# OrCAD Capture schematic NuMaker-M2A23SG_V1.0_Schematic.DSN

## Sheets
1 Nu-Link2-Me: size A3; title: Nu-Link2-Me; rev: 3.2; company: CMHuang; note: Nu-Link2-Me
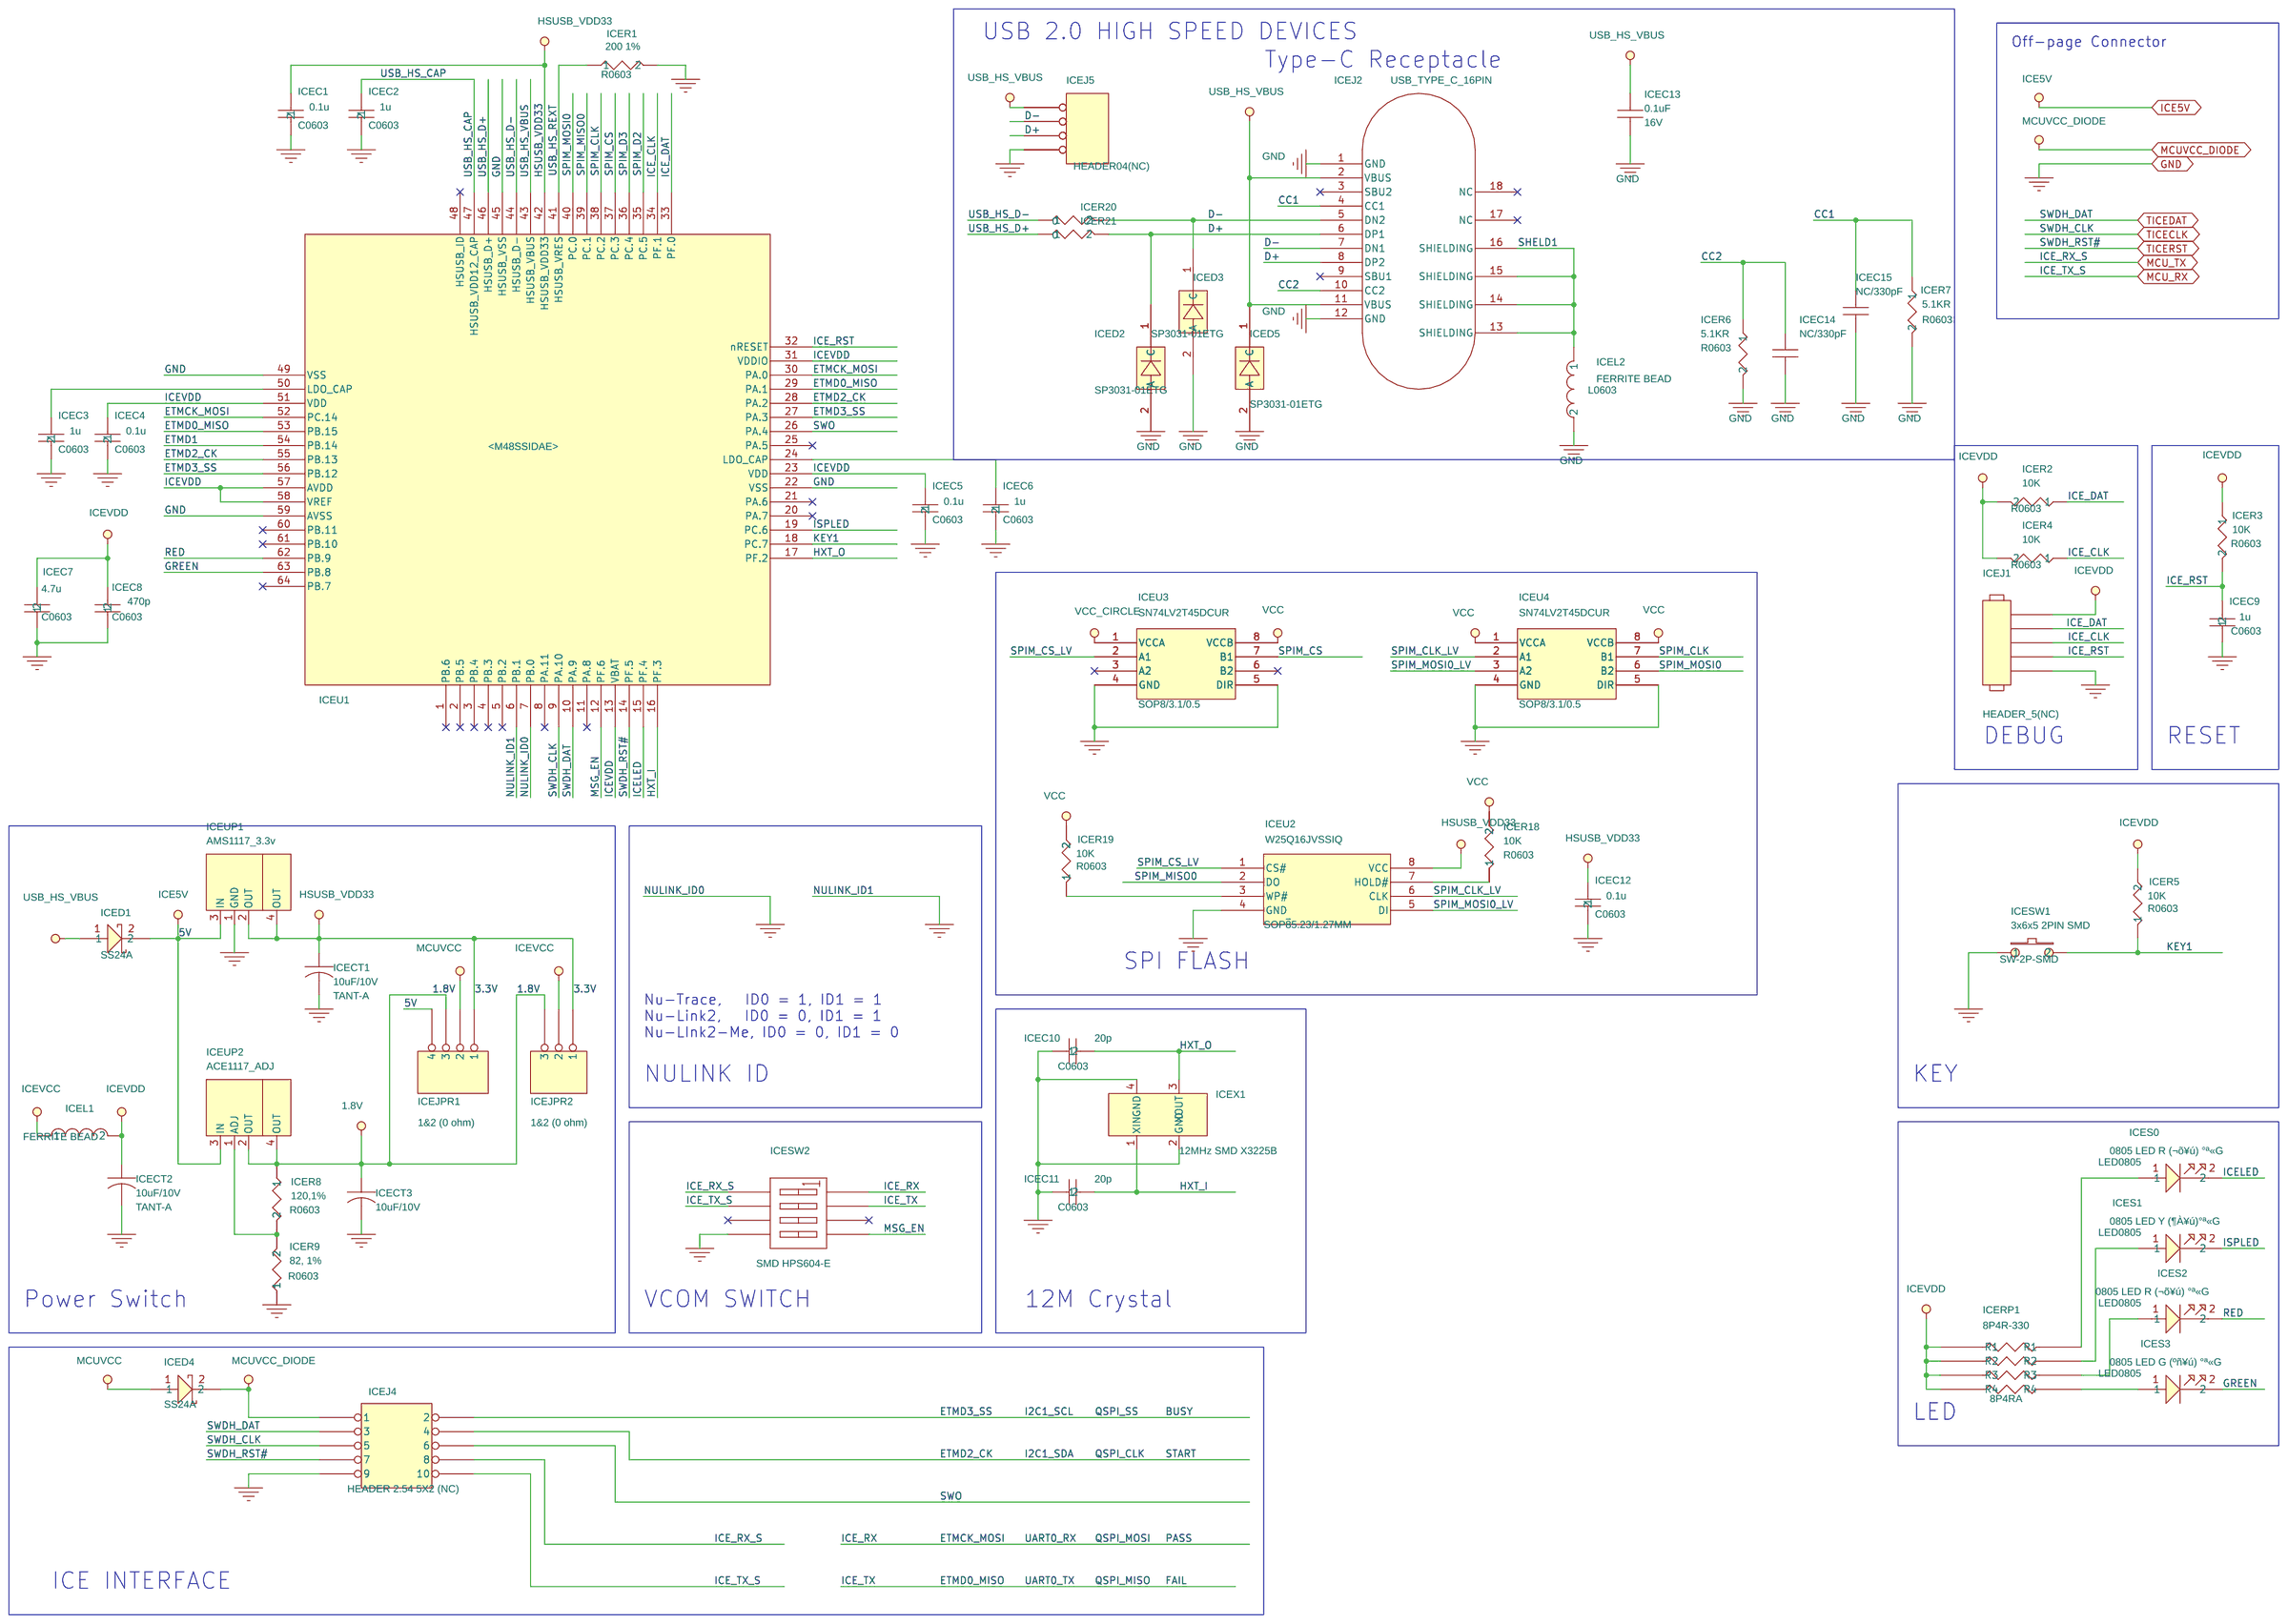
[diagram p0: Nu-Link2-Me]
2 M2A23: size Custom; title: M2A23SG5AC; rev: v1.0; note: NuMaker-M2A23SG
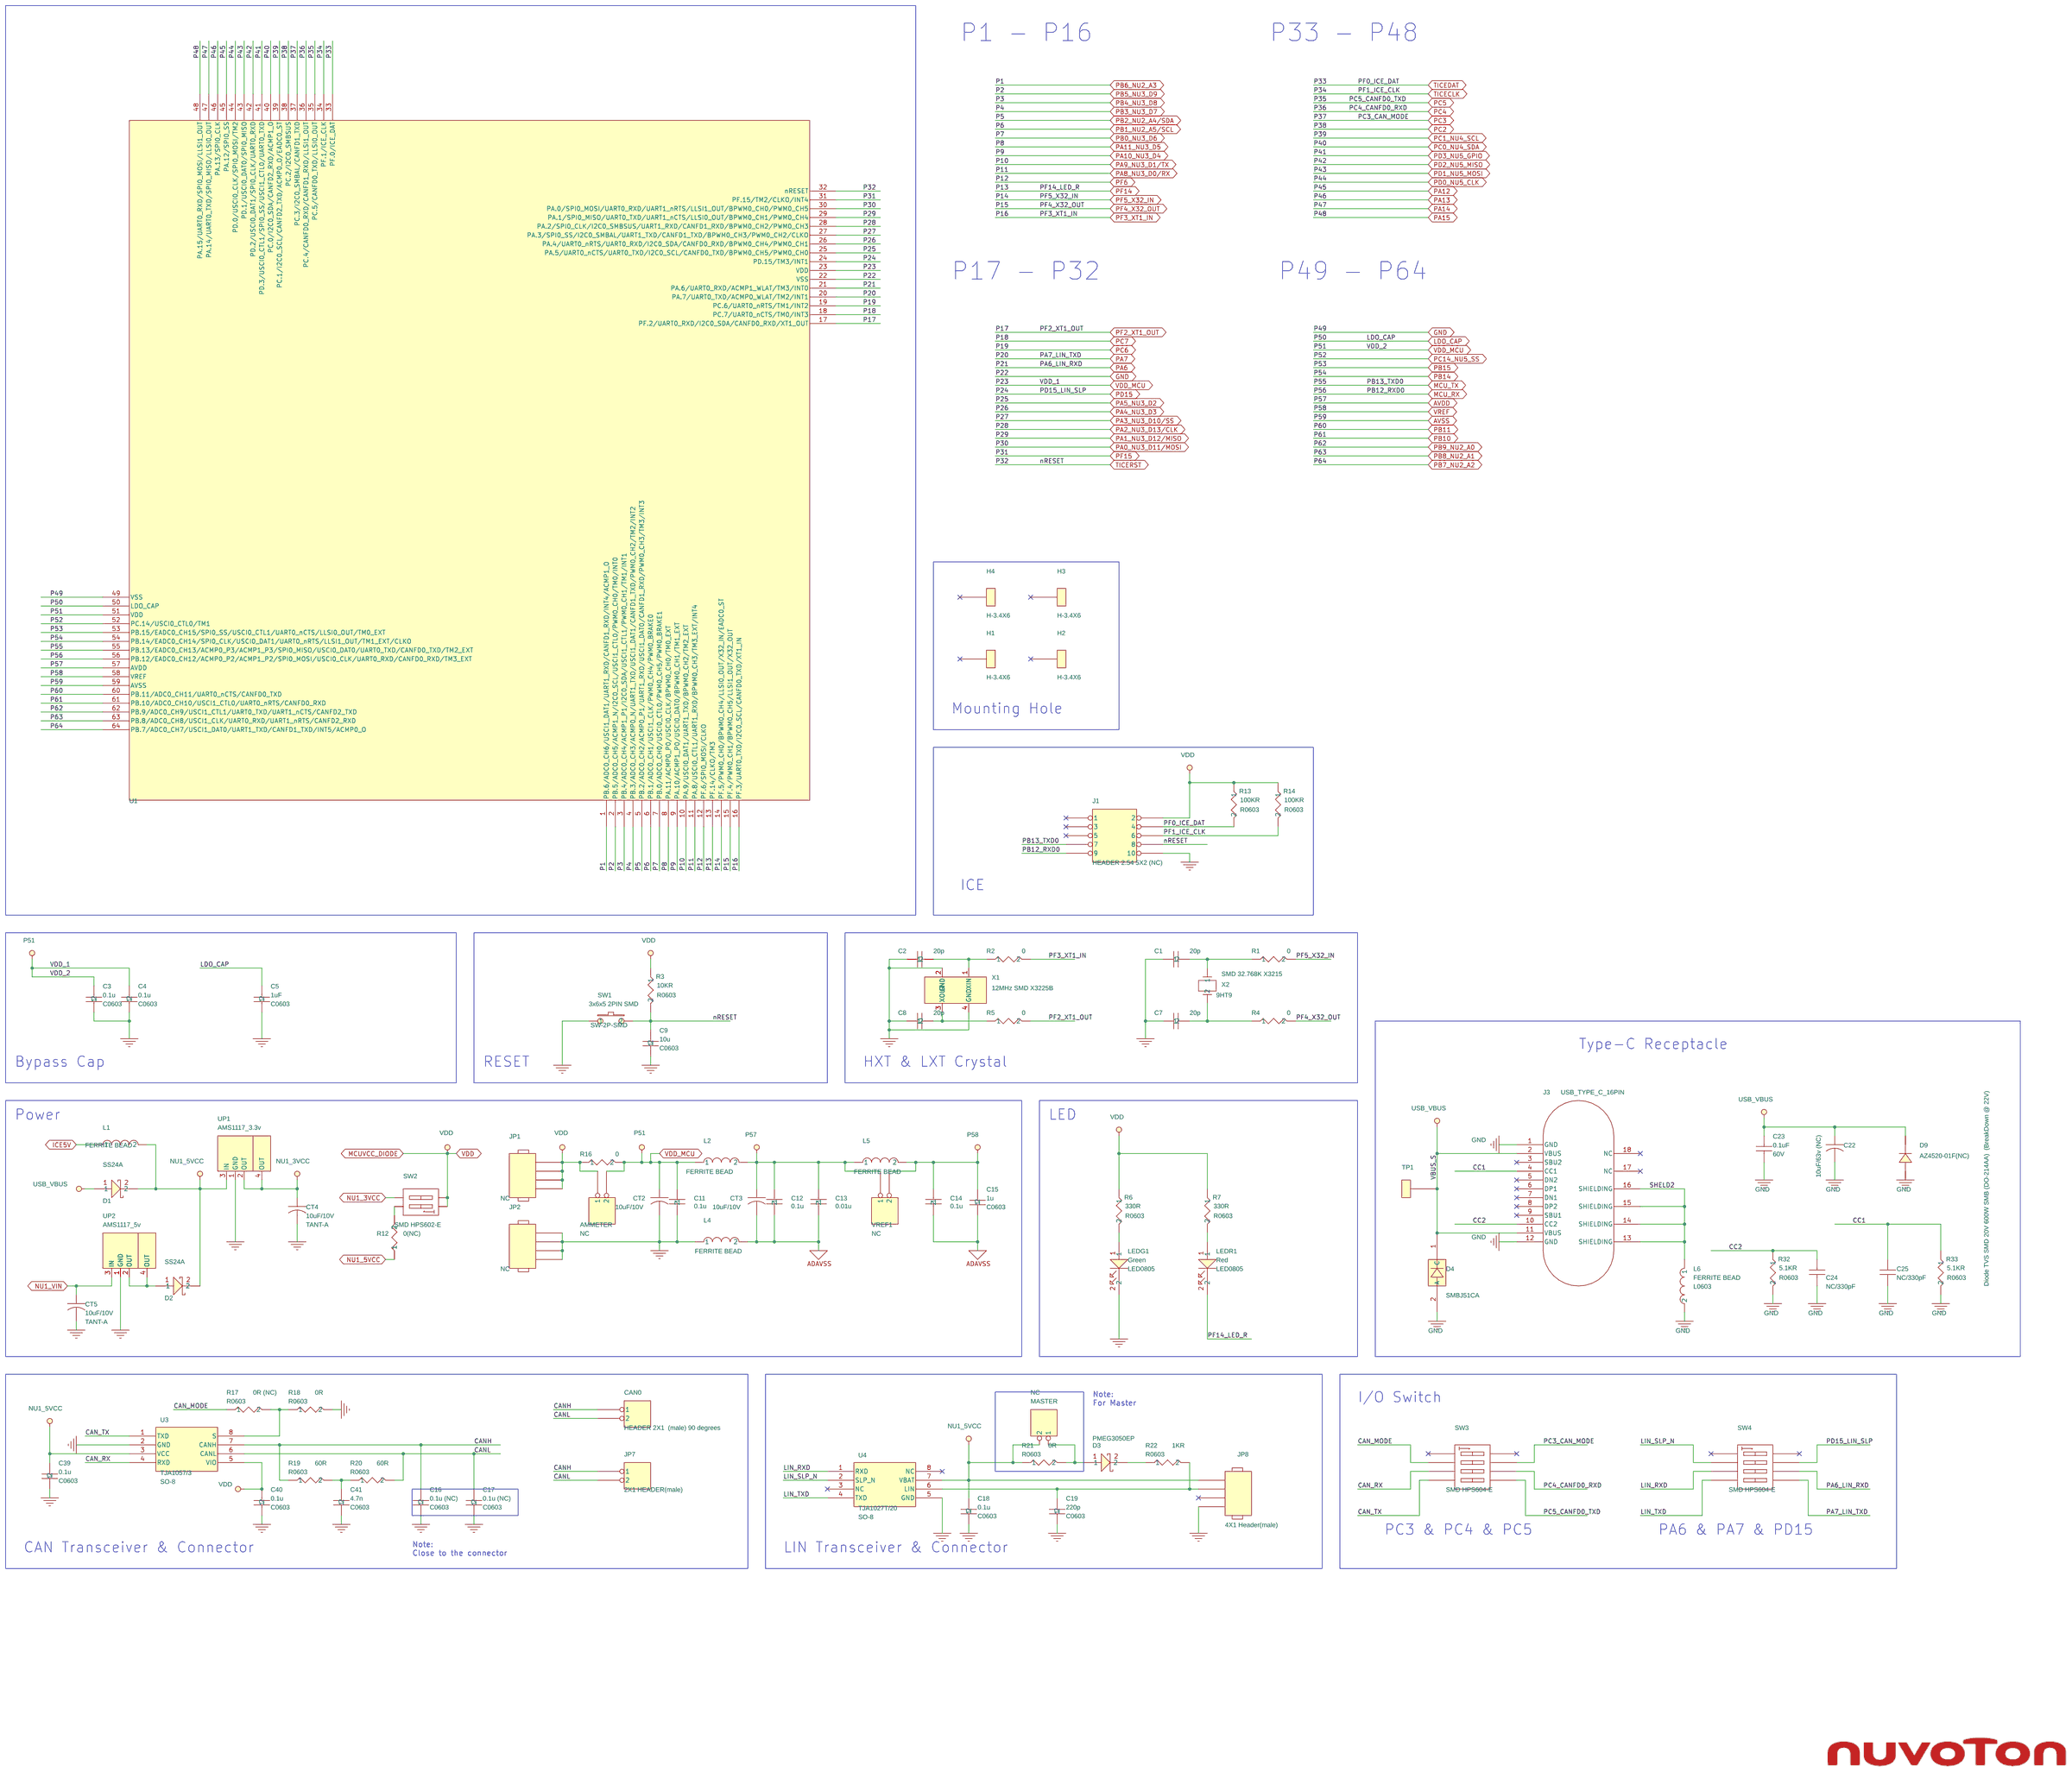
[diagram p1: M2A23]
3 Ext. Connector: size Custom; title: Ext. Connector; rev: v1.0; note: NuMaker-M2A23SG
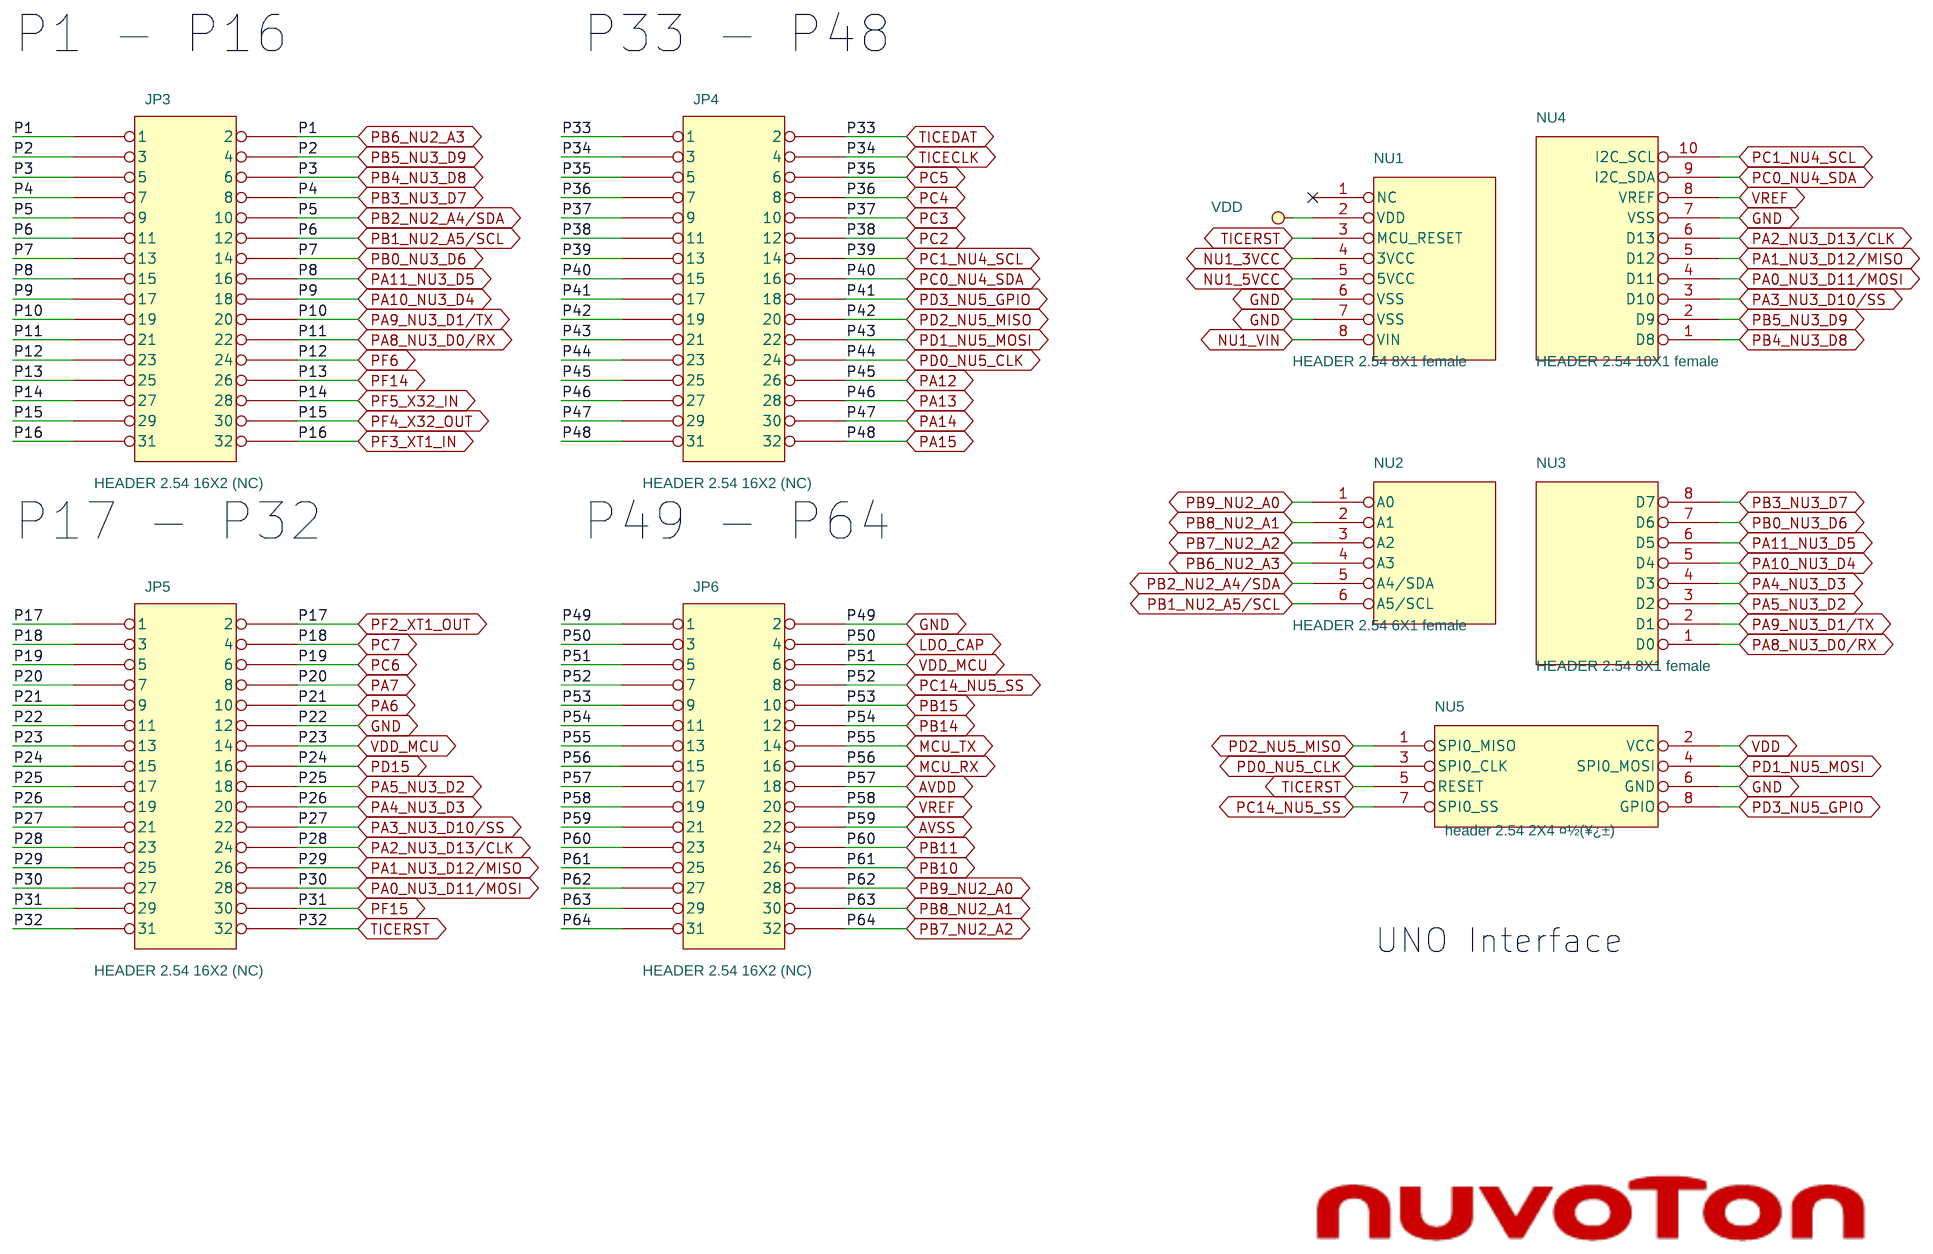
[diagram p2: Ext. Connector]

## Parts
sheet Ext. Connector
JP3  HEADER 2.54 16X2 (NC)  [HEADER16X2]
JP4  HEADER 2.54 16X2 (NC)  [HEADER16X2]
JP5  HEADER 2.54 16X2 (NC)  [HEADER16X2]
JP6  HEADER 2.54 16X2 (NC)  [HEADER16X2]
NU1  HEADER 2.54 8X1 female  [SIP-8P]
NU2  HEADER 2.54 6X1 female  [SIP-6P]
NU3  HEADER 2.54 8X1 female  [SIP-8P]
NU4  HEADER 2.54 10X1 female  [SIP-10P]
NU5  header 2.54 2X4 ¤½(¥¿­±)  [HEADER4X2]
sheet M2A23
AMMETER  NC  [HEADER2X1]
C1  20p  [C0603]
C2  20p  [C0603]
C3  0.1u  [C0603]
C4  0.1u  [C0603]
C5  1uF  [C0603]
C7  20p  [C0603]
C8  20p  [C0603]
C9  10u  [C0603]
C11  0.1u  [C0603]
C12  0.1u  [C0603]
C13  0.01u  [C0603]
C14  0.1u  [C0603]
C15  1u  [C0603]
C16  0.1u (NC)  [C0603]
C17  0.1u (NC)  [C0603]
C18  0.1u  [C0603]
C19  220p  [C0603]
C22  10uF/63v (NC)  [CES/6.3D/P]
C23  0.1uF  [C0603]
C24  NC/330pF  [C0603]
C25  NC/330pF  [C0603]
C39  0.1u  [C0603]
C40  0.1u  [C0603]
C41  4.7n  [C0603]
CAN0  HEADER 2X1  (male) 90 degrees  [SIP/2P_3.5MM]
CT2  10uF/10V  [TANT-A]
CT3  10uF/10V  [TANT-A]
CT4  10uF/10V  [TANT-A]
CT5  10uF/10V  [TANT-A]
D1  SS24A  [RB060L]
D2  SS24A  [RB060L]
D3  PMEG3050EP  [SOD-123-A(B)]
D4  SMBJ51CA  [DO-214AA]
D9  AZ4520-01F(NC)  [DO-214AA/SMB]
H1  H-3.4X6  [H-3.4X6]
H2  H-3.4X6  [H-3.4X6]
H3  H-3.4X6  [H-3.4X6]
H4  H-3.4X6  [H-3.4X6]
J1  HEADER 2.54 5X2 (NC)  [HEADER5X2]
J3  USB_TYPE_C_16PIN  [TID(00302-UCAF003-N)]
JP1  NC  [header1x4]
JP2  NC  [header1x4]
JP7  2X1 HEADER(male)  [HEADER2X1]
JP8  4X1 Header(male)  [header1x4]
L1  FERRITE BEAD  [L0603]
L2  FERRITE BEAD  [L0603]
L4  FERRITE BEAD  [L0603]
L5  FERRITE BEAD  [L0603]
L6  FERRITE BEAD  [L0603]
LEDG1  Green  [LED0805]
LEDR1  Red  [LED0805]
MASTER  NC  [HEADER2X1]
R1  0  [R0603]
R2  0  [R0603]
R3  10KR  [R0603]
R4  0  [R0603]
R5  0  [R0603]
R6  330R  [R0603]
R7  330R  [R0603]
R12  0(NC)  [R0603]
R13  100KR  [R0603]
R14  100KR  [R0603]
R16  0  [R0603]
R17  0R (NC)  [R0603]
R18  0R  [R0603]
R19  60R  [R0603]
R20  60R  [R0603]
R21  0R  [R0603]
R22  1KR  [R0603]
R32  5.1KR  [R0603]
R33  5.1KR  [R0603]
SW1  3x6x5 2PIN SMD  [SW-2P-SMD]
SW2  SMD HPS602-E  [SW1X2]
SW3  SMD HPS604-E  [SW1X4]
SW4  SMD HPS604-E  [SW1X4]
TP1  TEST_POINT
U1  M2A23SG5AC  [MCU_LQFP64_7X7mm]
U3  TJA1057/3  [SO-8]
U4  TJA1027T/20  [SO-8]
UP1  AMS1117_3.3v  [SOT-223-1]
UP2  AMS1117_5v  [SOT-223-1]
VREF1  NC  [HEADER2X1]
X1  12MHz SMD X3225B  [CRYSTAL_SMD]
X2  SMD 32.768K X3215  [9HT9]
sheet Nu-Link2-Me
ICEC1  0.1u  [C0603]
ICEC2  1u  [C0603]
ICEC3  1u  [C0603]
ICEC4  0.1u  [C0603]
ICEC5  0.1u  [C0603]
ICEC6  1u  [C0603]
ICEC7  4.7u  [C0603]
ICEC8  470p  [C0603]
ICEC9  1u  [C0603]
ICEC10  20p  [C0603]
ICEC11  20p  [C0603]
ICEC12  0.1u  [C0603]
ICEC13  0.1uF  [C0603]
ICEC14  NC/330pF  [C0603]
ICEC15  NC/330pF  [C0603]
ICECT1  10uF/10V  [TANT-A]
ICECT2  10uF/10V  [TANT-A]
ICECT3  10uF/10V  [TANT-A]
ICED1  SS24A  [RB060L]
ICED2  SP3031-01ETG  [SOD882]
ICED3  SP3031-01ETG  [SOD882]
ICED4  SS24A  [RB060L]
ICED5  SP3031-01ETG  [SOD882]
ICEJ1  HEADER_5(NC)  [HEADER5X1]
ICEJ2  USB_TYPE_C_16PIN  [TID(00302-UCAF003-N)]
ICEJ4  HEADER 2.54 5X2 (NC)  [HEADER5X2]
ICEJ5  HEADER04(NC)  [HEADER04]
ICEJPR1  1&2 (0 ohm)  [R0603X3]
ICEJPR2  1&2 (0 ohm)  [R0603X2]
ICEL1  FERRITE BEAD  [L0603]
ICEL2  FERRITE BEAD  [L0603]
ICER1  200 1%  [R0603]
ICER2  10K  [R0603]
ICER3  10K  [R0603]
ICER4  10K  [R0603]
ICER5  10K  [R0603]
ICER6  5.1KR  [R0603]
ICER7  5.1KR  [R0603]
ICER8  120,1%  [R0603]
ICER9  82, 1%  [R0603]
ICER18  10K  [R0603]
ICER19  10K  [R0603]
ICER20  0  [R0603]
ICER21  0  [R0603]
ICERP1  8P4R-330  [8P4RA]
ICES0  0805 LED R (¬õ¥ú) °ª«G  [LED0805]
ICES1  0805 LED Y (¶À¥ú)°ª«G  [LED0805]
ICES2  0805 LED R (¬õ¥ú) °ª«G  [LED0805]
ICES3  0805 LED G (ºñ¥ú) °ª«G  [LED0805]
ICESW1  3x6x5 2PIN SMD  [SW-2P-SMD]
ICESW2  SMD HPS604-E  [SW1X4]
ICEU1  M48SSIDAE  [LQFP64_7x7_M48SSIDAE]
ICEU2  W25Q16JVSSIQ  [SOP8\5.23/1.27MM]
ICEU3  SN74LV2T45DCUR  [SOP8/3.1/0.5]
ICEU4  SN74LV2T45DCUR  [SOP8/3.1/0.5]
ICEUP1  AMS1117_3.3v  [SOT-223-1]
ICEUP2  ACE1117_ADJ  [SOT-223-1]
ICEX1  12MHz SMD X3225B  [CRYSTAL_SMD]

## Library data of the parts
JP3 = HEADER_16X2_3
JP4 = HEADER_16X2
JP5 = HEADER_16X2_1
JP6 = HEADER_16X2_2
NU1 = POWER_CONNECT_0
NU2 = ADC_CONNECT_0
NU3 = PWM0_CONNECT_0
NU4 = PWM1_CONNECT_1
NU5 = NuEdu_NU7
AMMETER = HEADER_2
C1 = C_20p_2
C2 = C_20p_3
C3 = CAP-C_3: Package: 0603; element_no: C0004
C4 ICEC12 = CAP-C_7: Package: 0603; element_no: C0004
C5 = CAP-C_10: Package: 0603; element_no: C0006
C7 = C_20p
C8 = C_20p_1
C9 = CAP-C: Package: 0603; element_no: C0006
C11 = C_0.1u_2: element_no: C0004
C12 = C_0.1u_3: element_no: C0004
C13 = C_0.1u: element_no: C0003
C14 = C_0.1u_1: element_no: C0004
C15 = CAP-C_8: Package: 0603; element_no: C0006
C16 = CAP-C_6: Package: 0603; element_no: C0006
C17 = CAP-C_2: Package: 0603; element_no: C0006
C18 ICEC3 = CAP-C_11: Package: 0603; element_no: C0006
C19 ICEC9 = CAP-C_5: Package: 0603; element_no: C0006
C22 CT2-CT5 ICECT1-ICECT3 = C_10uF_10V
C23 = CAPACITOR_NP: CAP CER X7R SMD 0.1uF 10% 50V 0603; Mount: M; Part Number: 880600286; Part Type: Capacitor\Ceramic; Raing/Power: 60V; Tolerance: 10%
C24 C25 ICEC14 ICEC15 = CAPACITOR_NP: CAP CER NPO SMD 330pF 5% 50V 0603; Mount: M; Part Number: 880600252; Part Type: Capacitor\Ceramic; Raing/Power: 50V; Tolerance: 5%
C39 = CAP-C_4: Package: 0603; element_no: C0006
C40 = CAP-C_1: Package: 0603; element_no: C0006
C41 ICEC2 = CAP-C_9: Package: 0603; element_no: C0006
CAN0 = HEADER_2_2
D1 = D_SS24A_2
D2 ICED1 = D_SS24A
D3 ICED4 = D_SS24A_1
D4 = Schottky_Barrier_Diode_0: Diode SMD Schottky Barrier 30V; Mount: M; Part Number: 880900908
D9 = DIODE21: Diode TVS SMD 20V 600W SMB (DO-214AA)  (BreakDown @ 22V); Mount: M; Part Number: 880900866; Part Type: Diode
H1-H4 TP1 = TEST_POINT
ICEJ4 J1 = HEADER_5X2
J3 = USB_TYPE_C_9: CON USB 3.0 Type C receptical SMD & TH; Mount: M; Part Number: 880400981; Part Type: Connector
JP1 JP2 JP8 = HEADER_4_v2
JP7 = HEADER_2_3
L1 = FERRITE_BEAD_4
L2 = FERRITE_BEAD_2
ICEL1 L4 = FERRITE_BEAD_1
L5 = FERRITE_BEAD_3
ICEL2 L6 = FERRITE_BEAD
ICES2 LEDG1 = LED_0_1: Package: KP-2012; Vendor: Kingbright
ICES1 LEDR1 = LED_0: Package: KP-2012; Vendor: Kingbright
MASTER = HEADER_2_0
R1 = R_0_16
R2 = R_0_5
ICER6 R3 = R_0_10: Package: 0603
R4 = R_0_15
R5 = R_0_18
ICER7 R6 = R_0_6: Package: 0603
ICER8 R7 = R_0_3: Package: 0603
R12 = R_0_7
ICER5 R13 = R_0: Package: 0603
ICER2 R14 = R_0_2: Package: 0603
R16 = R_0_14
ICER19 R17 = R_0_1: Package: 0603
R18 = R_0_13: Package: 0603
R19 = R_0_11: Package: 0603
R20 = R_0_12: Package: 0603
ICER1 R21 = R_0_4: Package: 0603
ICER9 R22 = R_0_9: Package: 0603
R32 = R_0_17: Package: 0603
ICER4 R33 = R_0_8: Package: 0603
ICESW1 SW1 = SW_PUSHBUTTON_0
SW2 = SW_DIP-4_2
ICESW2 SW3 SW4 = SW_DIP-4_SM
U1 = M2A23SG5AC
U3 = TJA1057_3
U4 = TJA1027T_20
ICEUP1 UP1 UP2 = TO-247_Regulator_10
VREF1 = HEADER_2_1
ICEX1 X1 = Crystal_SMD_1
X2 = Xtal_32.768K
ICEC1 = CAP-C_8: Package: 0603; element_no: C0004
ICEC4 = CAP-C_1: Package: 0603; element_no: C0004
ICEC5 = CAP-C_4: Package: 0603; element_no: C0004
ICEC6 = CAP-C_3: Package: 0603; element_no: C0006
ICEC7 = CAP-C: Package: 0603
ICEC8 = CAP-C_6: Package: 0603
ICEC10 = CAP-C_2: Package: 0603
ICEC11 = CAP-C_10: Package: 0603
ICEC13 = CAPACITOR_NP: CAP CER X7R SMD 0.1uF 10% 50V 0603; Mount: M; Part Number: 880600286; Part Type: Capacitor\Ceramic; Raing/Power: 16V; Tolerance: 10%
ICED2 ICED3 ICED5 = Schottky_Barrier_Diode_1: Diode SMD Schottky Barrier 30V; Mount: M; Part Number: 880900908
ICEJ1 = HEADER_5
ICEJ2 = USB_TYPE_C_10: CON USB 3.0 Type C receptical SMD & TH; Mount: M; Part Number: 880400981; Part Type: Connector
ICEJ5 = HEADER_4
ICEJPR1 = HEADER_3_0
ICEJPR2 = HEADER_3
ICER3 = R_0_5: Package: 0603
ICER18 = R_0_7: Package: 0603
ICER20 = R_33_1
ICER21 = R_33
ICERP1 = R-PACK8_0
ICES0 = LED_0_3: Package: KP-2012; Vendor: Kingbright
ICES3 = LED_0_2: Package: KP-2012; Vendor: Kingbright
ICEU1 = M487SIDAE_0: M487SIDAE: <M48SSIDAE>
ICEU2 = W25P10_20_40_SOIC_0: Package: SOP8; Vendor: WINBOND
ICEU3 ICEU4 = SN74LV2T45
ICEUP2 = TO-247_Regulator_0

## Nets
1.8V: ICECT3.1 ICEJPR1.3 ICEJPR2.3 ICER8.1 ICEUP2.2(OUT) ICEUP2.4(OUT)
3.3V: ICEC1.1 ICEC12.1 ICECT1.1 ICEJPR1.1 ICEJPR2.1 ICER18.2 ICER19.2 ICEU1.42(HSUSB_VDD33) ICEU2.8(VCC) ICEU3.1(VCCA) ICEU4.1(VCCA) ICEUP1.2(OUT) ICEUP1.4(OUT)
AVDD: C12.1 C13.1 CT3.1 JP6.17 JP6.18 L2.2 L5.1 U1.57(AVDD) VREF1.1
AVSS: C12.2 C13.2 C14.2 C15.1 CT3.2 JP6.21 JP6.22 L4.2 U1.59(AVSS)
GND: C1.1 C2.1 C3.1 C4.1 C5.1 C7.1 C8.1 C9.1 C11.2 C16.1 C17.1 C18.1 C19.1 C22.2 C23.2 C24.2 C25.2 C39.1 C40.1 C41.1 CT2.2 CT4.2 CT5.2 D4.2(A) D9.2(A) ICEC1.2 ICEC2.2 ICEC3.2 ICEC4.2 ICEC5.2 ICEC6.2 ICEC7.1 ICEC8.1 ICEC9.1 ICEC10.1 ICEC11.1 ICEC12.2 ICEC13.2 ICEC14.2 ICEC15.2 ICECT1.2 ICECT2.2 ICECT3.2 ICED2.2(A) ICED3.2(A) ICED5.2(A) ICEJ1.5 ICEJ2.1(GND) ICEJ2.12(GND) ICEJ4.9 ICEJ5.4 ICEL2.2 ICER1.2 ICER6.2 ICER7.2 ICER9.1 ICESW1.1 ICESW2.4(A4) ICEU1.6(PB.1) ICEU1.7(PB.0) ICEU1.22(VSS) ICEU1.45(HSUSB_VSS) ICEU1.49(VSS) ICEU1.59(AVSS) ICEU2.4(GND) ICEU3.4(GND) ICEU3.5(DIR) ICEU4.4(GND) ICEU4.5(DIR) ICEUP1.1(GND) ICEX1.2(GND) ICEX1.4(GND) J1.10 J3.1(GND) J3.12(GND) JP2.1 JP2.2 JP2.3 JP2.4 JP5.11 JP5.12 JP6.1 JP6.2 JP8.4 L4.1 L6.2 LEDG1.2 NU1.6(VSS) NU1.7(VSS) NU4.7(VSS) NU5.6(GND) R18.2 R32.2 R33.2 SW1.1 U1.22(VSS) U1.49(VSS) U3.2(GND) U4.5(GND) UP1.1(GND) UP2.1(GND) X1.2(GND) X1.4(GND)
VDD: AMMETER.1 C40.2 ICED4.2 ICEJ4.1 J1.2 JP1.1 JP1.2 JP1.3 JP1.4 NU1.2(VDD) NU5.2(VCC) R3.1 R6.1 R7.1 R13.1 R14.1 R16.1 SW2.3(B1) SW2.4(B2) U3.5(VIO)
VDD_MCU: AMMETER.2 C3.2 C4.2 C11.1 CT2.1 JP5.13 JP5.14 JP6.5 JP6.6 L2.1 R16.2 U1.23(VDD) U1.51(VDD)
BUSY: ICEJ4.2 ICEU1.27(PA.3) ICEU1.56(PB.12)
CAN_MODE: R17.1 SW3.7(B2)
CAN_RX: SW3.6(B3) U3.4(RXD)
CAN_TX: SW3.5(B4) U3.1(TXD)
CANH: C16.2 CAN0.1 JP7.1 R19.1 U3.7(CANH)
CANL: C17.2 CAN0.2 JP7.2 R20.2 U3.6(CANL)
CC1: ICEC15.1 ICEJ2.4(CC1) ICER7.1
CC1 (page 02-M2A23): C25.1 J3.4(CC1) R33.1
CC2: ICEC14.1 ICEJ2.10(CC2) ICER6.1
CC2 (page 02-M2A23): C24.1 J3.10(CC2) R32.1
D+: ICED2.1(C) ICEJ2.6(DP1) ICEJ2.8(DP2) ICEJ5.3 ICER21.2
D-: ICED3.1(C) ICEJ2.5(DN2) ICEJ2.7(DN1) ICEJ5.2 ICER20.2
ETMD1: ICEU1.54(PB.14)
ETMD2_CK: ICEJ4.4 ICEU1.28(PA.2) ICEU1.55(PB.13)
GREEN: ICES3.2 ICEU1.63(PB.8)
HXT_I: ICEC11.2 ICEU1.16(PF.3) ICEX1.1(XIN)
HXT_O: ICEC10.2 ICEU1.17(PF.2) ICEX1.3(XOUT)
ICE5V: ICED1.2 ICEJPR1.4 ICEUP1.3(IN) ICEUP2.3(IN) L1.1
ICE_CLK: ICEJ1.3 ICER4.1 ICEU1.34(PF.1)
ICE_DAT: ICEJ1.2 ICER2.1 ICEU1.33(PF.0)
ICE_RST: ICEC9.2 ICEJ1.4 ICER3.2 ICEU1.32(nRESET)
ICE_RX: ICESW2.8(B1) ICEU1.30(PA.0) ICEU1.52(PC.14)
ICE_TX: ICESW2.7(B2) ICEU1.29(PA.1) ICEU1.53(PB.15)
ICELED: ICES0.2 ICEU1.15(PF.4)
ICEVCC: ICEJPR2.2 ICEL1.1
ICEVDD: ICEC4.1 ICEC5.1 ICEC7.2 ICEC8.2 ICECT2.1 ICEJ1.1 ICEL1.2 ICER2.2 ICER3.1 ICER4.2 ICER5.2 ICERP1.1(R1) ICERP1.3(R2) ICERP1.5(R3) ICERP1.7(R4) ICEU1.13(VBAT) ICEU1.23(VDD) ICEU1.31(VDDIO) ICEU1.51(VDD) ICEU1.57(AVDD) ICEU1.58(VREF) ICEU3.8(VCCB) ICEU4.8(VCCB)
ISPLED: ICES1.2 ICEU1.19(PC.6)
KEY1: ICER5.1 ICESW1.2 ICEU1.18(PC.7)
LDO_CAP: C5.2 JP6.3 JP6.4 U1.50(LDO_CAP)
LIN_RXD: SW4.6(B3) U4.1(RXD)
LIN_SLP_N: SW4.7(B2) U4.2(SLP_N)
LIN_TXD: SW4.5(B4) U4.4(TXD)
MCU_RX: ICEJ4.10 ICESW2.2(A2) J1.9 JP6.15 JP6.16 U1.56(PB.12/EADC0_CH12/ACMP0_P2/ACMP1_P2/SPI0_MOSI/USCI0_CLK/UART0_RXD/CANFD0_RXD/TM3_EXT)
MCU_TX: ICEJ4.8 ICESW2.1(A1) J1.7 JP6.13 JP6.14 U1.55(PB.13/EADC0_CH13/ACMP0_P3/ACMP1_P3/SPI0_MISO/USCI0_DAT0/UART0_TXD/CANFD0_TXD/TM2_EXT)
MCUVCC: ICED4.1 ICEJPR1.2
MSG_EN: ICESW2.5(B4) ICEU1.12(PF.6)
NU1_3VCC: CT4.1 NU1.4(3VCC) SW2.2(A2) UP1.2(OUT) UP1.4(OUT)
NU1_5VCC: C18.2 C39.2 D1.2 D2.2 JP8.1 L1.2 MASTER.2 NU1.5(5VCC) R12.1 R21.1 U3.3(VCC) U4.7(VBAT) UP1.3(IN)
NU1_VIN: CT5.1 NU1.8(VIN) UP2.3(IN)
PA0_NU3_D11/MOSI: JP5.27 JP5.28 NU4.4(D11) U1.30(PA.0/SPI0_MOSI/UART0_RXD/UART1_nRTS/LLSI1_OUT/BPWM0_CH0/PWM0_CH5)
PA1_NU3_D12/MISO: JP5.25 JP5.26 NU4.5(D12) U1.29(PA.1/SPI0_MISO/UART0_TXD/UART1_nCTS/LLSI0_OUT/BPWM0_CH1/PWM0_CH4)
PA2_NU3_D13/CLK: JP5.23 JP5.24 NU4.6(D13) U1.28(PA.2/SPI0_CLK/I2C0_SMBSUS/UART1_RXD/CANFD1_RXD/BPWM0_CH2/PWM0_CH3)
PA3_NU3_D10/SS: JP5.21 JP5.22 NU4.3(D10) U1.27(PA.3/SPI0_SS/I2C0_SMBAL/UART1_TXD/CANFD1_TXD/BPWM0_CH3/PWM0_CH2/CLKO)
PA4_NU3_D3: JP5.19 JP5.20 NU3.4(D3) U1.26(PA.4/UART0_nRTS/UART0_RXD/I2C0_SDA/CANFD0_RXD/BPWM0_CH4/PWM0_CH1)
PA5_NU3_D2: JP5.17 JP5.18 NU3.3(D2) U1.25(PA.5/UART0_nCTS/UART0_TXD/I2C0_SCL/CANFD0_TXD/BPWM0_CH5/PWM0_CH0)
PA6: JP5.9 JP5.10 SW4.3(A3) U1.21(PA.6/UART0_RXD/ACMP1_WLAT/TM3/INT0)
PA7: JP5.7 JP5.8 SW4.4(A4) U1.20(PA.7/UART0_TXD/ACMP0_WLAT/TM2/INT1)
PA8_NU3_D0/RX: JP3.21 JP3.22 NU3.1(D0) U1.11(PA.8/USCI0_CTL1/UART1_RXD/BPWM0_CH3/TM3_EXT/INT4)
PA9_NU3_D1/TX: JP3.19 JP3.20 NU3.2(D1) U1.10(PA.9/USCI0_DAT1/UART1_TXD/BPWM0_CH2/TM2_EXT)
PA10_NU3_D4: JP3.17 JP3.18 NU3.5(D4) U1.9(PA.10/ACMP1_P0/USCI0_DAT0/BPWM0_CH1/TM1_EXT)
PA11_NU3_D5: JP3.15 JP3.16 NU3.6(D5) U1.8(PA.11/ACMP0_P0/USCI0_CLK/BPWM0_CH0/TM0_EXT)
PA12: JP4.25 JP4.26 U1.45(PA.12/SPI0_SS)
PA13: JP4.27 JP4.28 U1.46(PA.13/SPI0_CLK)
PA14: JP4.29 JP4.30 U1.47(PA.14/UART0_TXD/SPI0_MISO/LLSI0_OUT)
PA15: JP4.31 JP4.32 U1.48(PA.15/UART0_RXD/SPI0_MOSI/LLSI1_OUT)
PB0_NU3_D6: JP3.13 JP3.14 NU3.7(D6) U1.7(PB.0/ADC0_CH0/USCI0_CTL0/PWM0_CH5/PWM0_BRAKE1)
PB1_NU2_A5/SCL: JP3.11 JP3.12 NU2.6(A5/SCL) U1.6(PB.1/ADC0_CH1/USCI1_CLK/PWM0_CH4/PWM0_BRAKE0)
PB2_NU2_A4/SDA: JP3.9 JP3.10 NU2.5(A4/SDA) U1.5(PB.2/ADC0_CH2/ACMP0_P1/UART1_RXD/USCI1_DAT0/CANFD1_RXD/PWM0_CH3/TM3/INT3)
PB3_NU3_D7: JP3.7 JP3.8 NU3.8(D7) U1.4(PB.3/ADC0_CH3/ACMP0_N/UART1_TXD/USCI1_DAT1/CANFD1_TXD/PWM0_CH2/TM2/INT2)
PB4_NU3_D8: JP3.5 JP3.6 NU4.1(D8) U1.3(PB.4/ADC0_CH4/ACMP1_P1/I2C0_SDA/USCI1_CTL1/PWM0_CH1/TM1/INT1)
PB5_NU3_D9: JP3.3 JP3.4 NU4.2(D9) U1.2(PB.5/ADC0_CH5/ACMP1_N/I2C0_SCL/USCI1_CTL0/PWM0_CH0/TM0/INT0)
PB6_NU2_A3: JP3.1 JP3.2 NU2.4(A3) U1.1(PB.6/ADC0_CH6/USCI1_DAT1/UART1_RXD/CANFD1_RXD/INT4/ACMP1_O)
PB7_NU2_A2: JP6.31 JP6.32 NU2.3(A2) U1.64(PB.7/ADC0_CH7/USCI1_DAT0/UART1_TXD/CANFD1_TXD/INT5/ACMP0_O)
PB8_NU2_A1: JP6.29 JP6.30 NU2.2(A1) U1.63(PB.8/ADC0_CH8/USCI1_CLK/UART0_RXD/UART1_nRTS/CANFD2_RXD)
PB9_NU2_A0: JP6.27 JP6.28 NU2.1(A0) U1.62(PB.9/ADC0_CH9/USCI1_CTL1/UART0_TXD/UART1_nCTS/CANFD2_TXD)
PB10: JP6.25 JP6.26 U1.61(PB.10/ADC0_CH10/USCI1_CTL0/UART0_nRTS/CANFD0_RXD)
PB11: JP6.23 JP6.24 U1.60(PB.11/ADC0_CH11/UART0_nCTS/CANFD0_TXD)
PB14: JP6.11 JP6.12 U1.54(PB.14/EADC0_CH14/SPI0_CLK/USCI0_DAT1/UART0_nRTS/LLSI1_OUT/TM1_EXT/CLKO)
PB15: JP6.9 JP6.10 U1.53(PB.15/EADC0_CH15/SPI0_SS/USCI0_CTL1/UART0_nCTS/LLSI0_OUT/TM0_EXT)
PC0_NU4_SDA: JP4.15 JP4.16 NU4.9(I2C_SDA) U1.40(PC.0/I2C0_SDA/CANFD2_RXD/ACMP1_O)
PC1_NU4_SCL: JP4.13 JP4.14 NU4.10(I2C_SCL) U1.39(PC.1/I2C0_SCL/CANFD2_TXD/ACMP0_O/EADC0_ST)
PC2: JP4.11 JP4.12 U1.38(PC.2/I2C0_SMBSUS)
PC3: JP4.9 JP4.10 SW3.2(A2) U1.37(PC.3/I2C0_SMBAL/CANFD1_TXD)
PC4: JP4.7 JP4.8 SW3.3(A3) U1.36(PC.4/CANFD0_RXD/CANFD1_RXD/LLSI1_OUT)
PC5: JP4.5 JP4.6 SW3.4(A4) U1.35(PC.5/CANFD0_TXD/LLSI0_OUT)
PC6: JP5.5 JP5.6 U1.19(PC.6/UART0_nRTS/TM1/INT2)
PC7: JP5.3 JP5.4 U1.18(PC.7/UART0_nCTS/TM0/INT3)
PC14_NU5_SS: JP6.7 JP6.8 NU5.7(SPI0_SS) U1.52(PC.14/USCI0_CTL0/TM1)
PD0_NU5_CLK: JP4.23 JP4.24 NU5.3(SPI0_CLK) U1.44(PD.0/USCI0_CLK/SPI0_MOSI/TM2)
PD1_NU5_MOSI: JP4.21 JP4.22 NU5.4(SPI0_MOSI) U1.43(PD.1/USCI0_DAT0/SPI0_MISO)
PD2_NU5_MISO: JP4.19 JP4.20 NU5.1(SPI0_MISO) U1.42(PD.2/USCI0_DAT1/SPI0_CLK/UART0_RXD)
PD3_NU5_GPIO: JP4.17 JP4.18 NU5.8(GPIO) U1.41(PD.3/USCI0_CTL1/SPI0_SS/USCI1_CTL0/UART0_TXD)
PD15: JP5.15 JP5.16 SW4.2(A2) U1.24(PD.15/TM3/INT1)
PF2_XT1_OUT: JP5.1 JP5.2 R5.2 U1.17(PF.2/UART0_RXD/I2C0_SDA/CANFD0_RXD/XT1_OUT)
PF3_XT1_IN: JP3.31 JP3.32 R2.2 U1.16(PF.3/UART0_TXD/I2C0_SCL/CANFD0_TXD/XT1_IN)
PF4_X32_OUT: JP3.29 JP3.30 R4.2 U1.15(PF.4/PWM0_CH1/BPWM0_CH5/LLSI1_OUT/X32_OUT)
PF5_X32_IN: JP3.27 JP3.28 R1.2 U1.14(PF.5/PWM0_CH0/BPWM0_CH4/LLSI0_OUT/X32_IN/EADC0_ST)
PF6: JP3.23 JP3.24 U1.12(PF.6/SPI0_MOSI/CLKO)
PF14: JP3.25 JP3.26 LEDR1.2 U1.13(PF.14/CLKO/TM3)
PF15: JP5.29 JP5.30 U1.31(PF.15/TM2/CLKO/INT4)
RED: ICES2.2 ICEU1.62(PB.9)
SHELD1: ICEJ2.13(SHIELDING) ICEJ2.14(SHIELDING) ICEJ2.15(SHIELDING) ICEJ2.16(SHIELDING) ICEL2.1
SHELD2: J3.13(SHIELDING) J3.14(SHIELDING) J3.15(SHIELDING) J3.16(SHIELDING) L6.1
SPIM_CLK: ICEU1.38(PC.2) ICEU4.7(B1)
SPIM_CLK_LV: ICEU2.6(CLK) ICEU4.2(A1)
SPIM_CS: ICEU1.37(PC.3) ICEU3.7(B1)
SPIM_CS_LV: ICEU2.1(CS#) ICEU3.2(A1)
SPIM_D2: ICEU1.35(PC.5)
SPIM_D3: ICEU1.36(PC.4)
SPIM_MISO0: ICEU1.39(PC.1) ICEU2.2(DO)
SPIM_MOSI0: ICEU1.40(PC.0) ICEU4.6(B2)
SPIM_MOSI0_LV: ICEU2.5(DI) ICEU4.3(A2)
SWO: ICEJ4.6 ICEU1.26(PA.4)
TICECLK: ICEJ4.5 ICEU1.9(PA.10) J1.6 JP4.3 JP4.4 R14.2 U1.34(PF.1/ICE_CLK)
TICEDAT: ICEJ4.3 ICEU1.10(PA.9) J1.4 JP4.1 JP4.2 R13.2 U1.33(PF.0/ICE_DAT)
TICERST: C9.2 ICEJ4.7 ICEU1.14(PF.5) J1.8 JP5.31 JP5.32 NU1.3(MCU_RESET) NU5.5(RESET) R3.2 SW1.2 U1.32(nRESET)
USB_HS_CAP: ICEC2.1 ICEU1.47(HSUSB_VDD12_CAP)
USB_HS_D+: ICER21.1 ICEU1.46(HSUSB_D+)
USB_HS_D-: ICER20.1 ICEU1.44(HSUSB_D-)
USB_HS_REXT: ICER1.1 ICEU1.41(HSUSB_VRES)
USB_HS_VBUS: ICEC13.1 ICED1.1 ICED5.1(C) ICEJ2.2(VBUS) ICEJ2.11(VBUS) ICEJ5.1 ICEU1.43(HSUSB_VBUS)
USB_VBUS: C22.1 C23.1 D1.1 D4.1(C) D9.1(K) J3.2(VBUS) J3.11(VBUS) TP1.1
VREF: C14.1 C15.2 JP6.19 JP6.20 L5.2 NU4.8(VREF) U1.58(VREF) VREF1.2
N16840819: ICEC6.1 ICEU1.24(LDO_CAP)
N16840960: ICEC3.1 ICEU1.50(LDO_CAP)
N17019924: ICER8.2 ICER9.2 ICEUP2.1(ADJ)
N17029977: ICERP1.8(R4) ICES3.1
N17029979: ICERP1.6(R3) ICES2.1
N17030004: ICERP1.4(R2) ICES1.1
N17030010: ICERP1.2(R1) ICES0.1
N17155328: ICER18.1 ICEU2.7(HOLD#)
N17155343: ICER19.1 ICEU2.3(WP#)
N17266321: LEDG1.1 R6.2
N17266323: LEDR1.1 R7.2
N17345296: C8.2 R5.1 X1.3(XOUT)
N17345298: C2.2 R2.1 X1.1(XIN)
N17345390: C1.2 R1.1 X2.1
N17345392: C7.2 R4.1 X2.2
N17392834: R12.2 SW2.1(A1)
N17392872: D2.1 UP2.2(OUT) UP2.4(OUT)
N17407390: C41.2 R19.2 R20.1
N17407472: R17.2 R18.1 U3.8(S)
N17407543: C19.2 JP8.2 R22.2 U4.6(LIN)
N17407646: D3.2 R22.1
N17407685: D3.1 MASTER.1 R21.2

Not connected (* = marked no-connect by the designer): H1 1*; H2 1*; H3 1*; H4 1*; ICEJ2 3(SBU2)* 9(SBU1)* 17(NC)* 18(NC)*; ICESW2 3(A3)* 6(B3)*; ICEU1 1(PB.6)* 2(PB.5)* 3(PB.4)* 4(PB.3)* 5(PB.2)* 8(PA.11)* 11(PA.8)* 20(PA.7)* 21(PA.6)* 25(PA.5)* 48(HSUSB_ID)* 60(PB.11)* 61(PB.10)* 64(PB.7)*; ICEU3 3(A2)* 6(B2)*; J1 1* 3* 5*; J3 3(SBU2)* 5(DN2)* 6(DP1)* 7(DN1)* 8(DP2)* 9(SBU1)* 17(NC)* 18(NC)*; JP8 3*; NU1 1(NC)*; SW3 1(A1)* 8(B1)*; SW4 1(A1)* 8(B1)*; U4 3(NC)* 8(NC)*

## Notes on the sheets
sheet 1
- USB 2.0 HIGH SPEED DEVICES
- Off-page Connector
- Type-C Receptacle
- DEBUG
- RESET
- SPI FLASH
- Nu-Trace,   ID0 = 1, ID1 = 1
  Nu-Link2,   ID0 = 0, ID1 = 1
  Nu-LInk2-Me, ID0 = 0, ID1 = 0
- NULINK ID
- KEY
- Power Switch
- VCOM SWITCH
- 12M Crystal
- LED
- ICE INTERFACE
sheet 2
- P1 - P16
- P33 - P48
- P17 - P32
- P49 - P64
- Mounting Hole
- ICE
- Type-C Receptacle
- Bypass Cap
- RESET
- HXT & LXT Crystal
- Power
- LED
- Note:
  For Master
- I/O Switch
- PC3 & PC4 & PC5
- PA6 & PA7 & PD15
- CAN Transceiver & Connector
- Note:
  Close to the connector
- LIN Transceiver & Connector
sheet 3
- P1 - P16
- P33 - P48
- P17 - P32
- P49 - P64
- UNO Interface
